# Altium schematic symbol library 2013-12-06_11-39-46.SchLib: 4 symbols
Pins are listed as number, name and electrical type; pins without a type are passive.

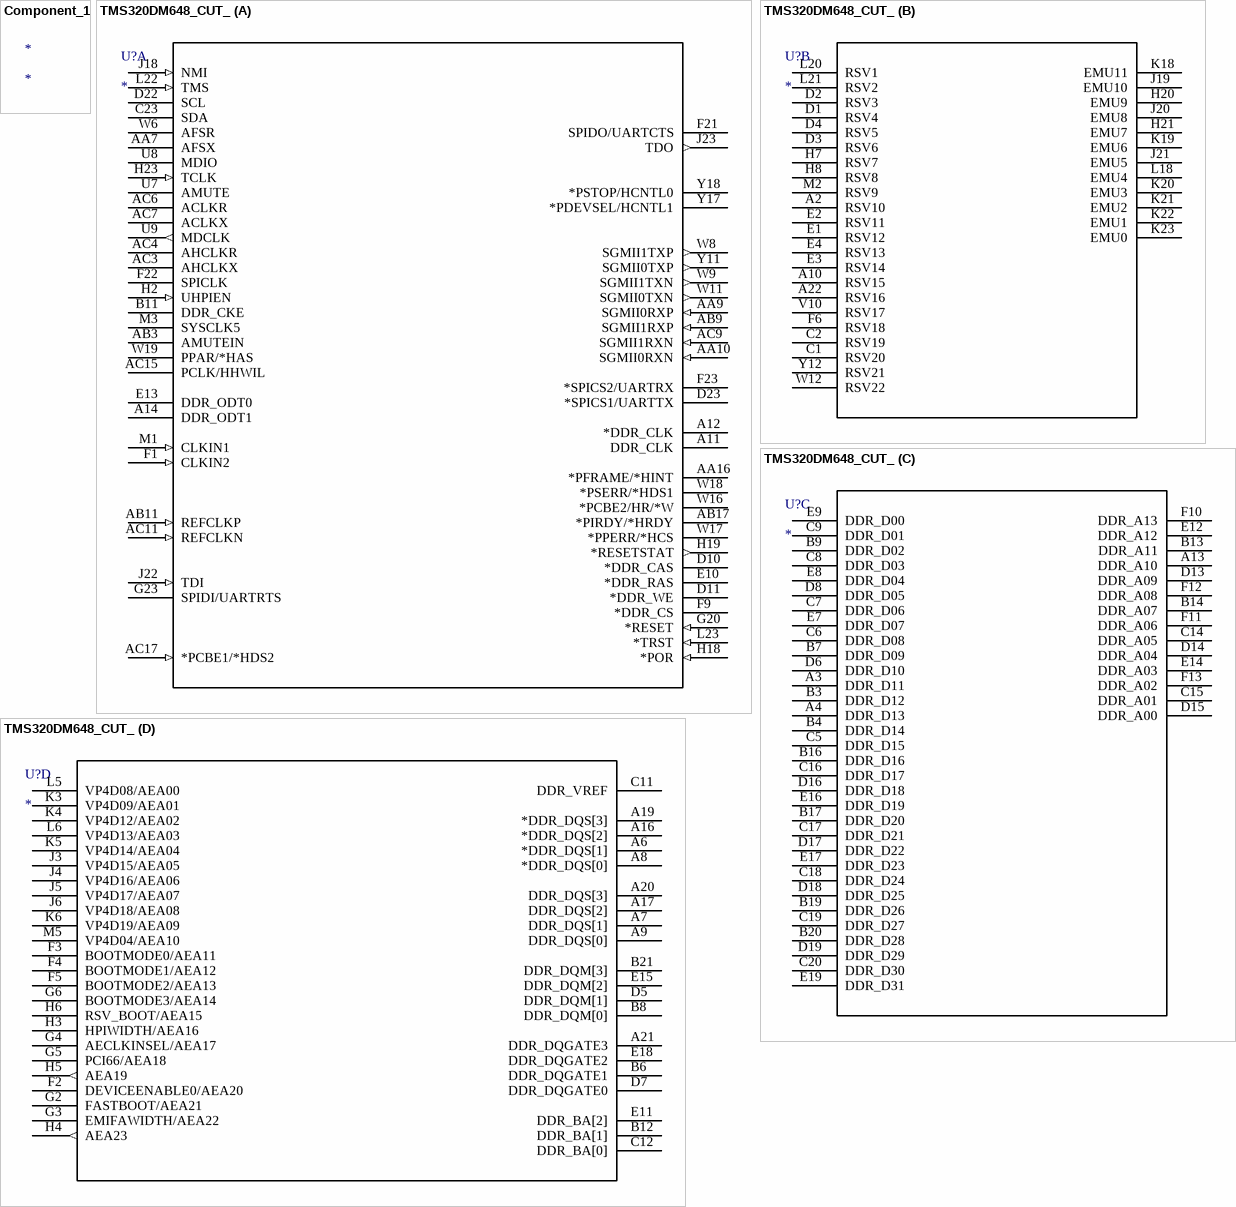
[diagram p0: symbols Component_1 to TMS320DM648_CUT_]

## Component_1
designator *

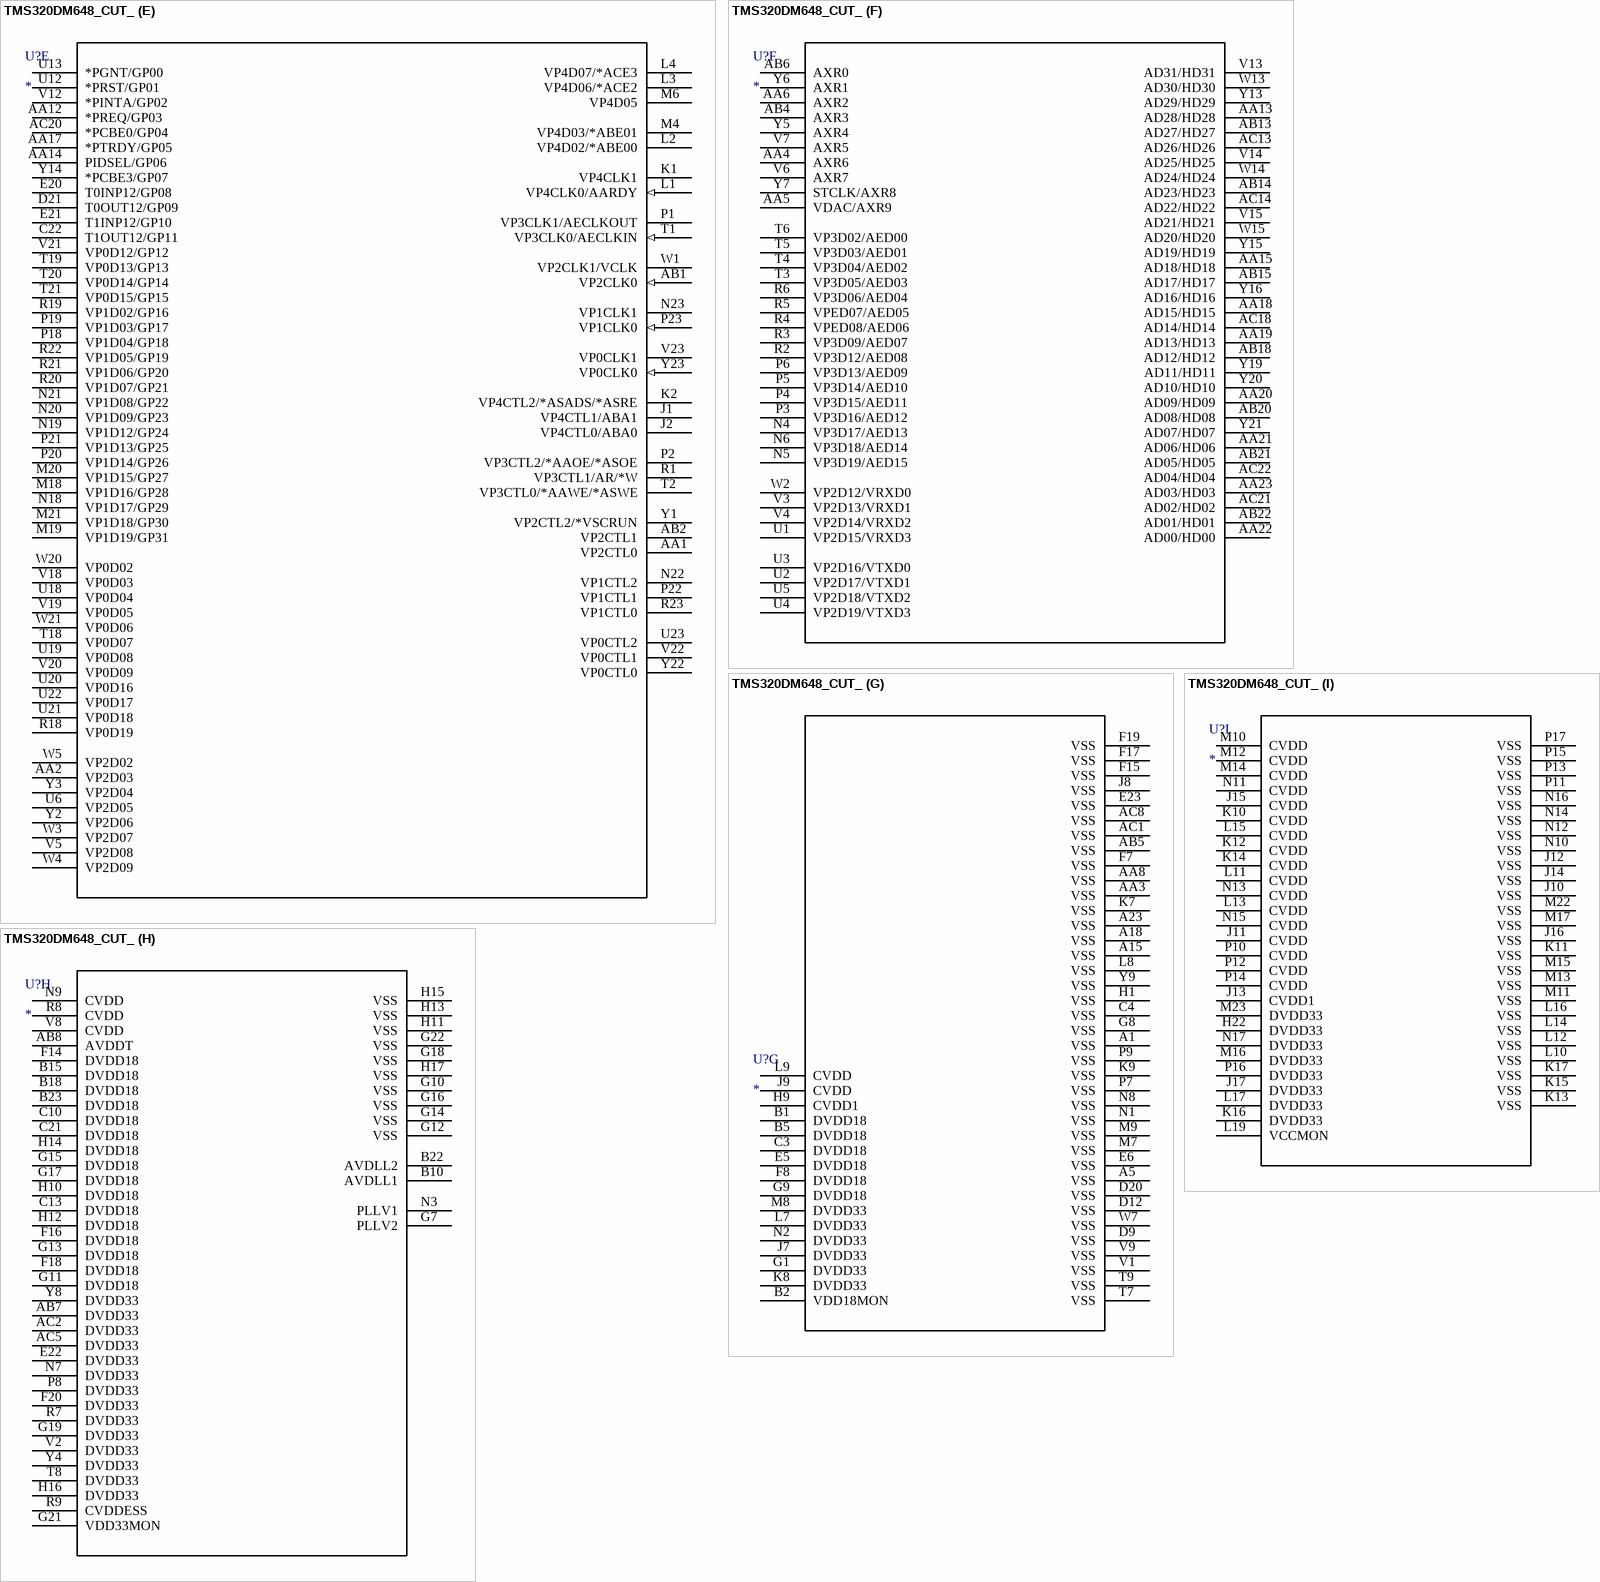
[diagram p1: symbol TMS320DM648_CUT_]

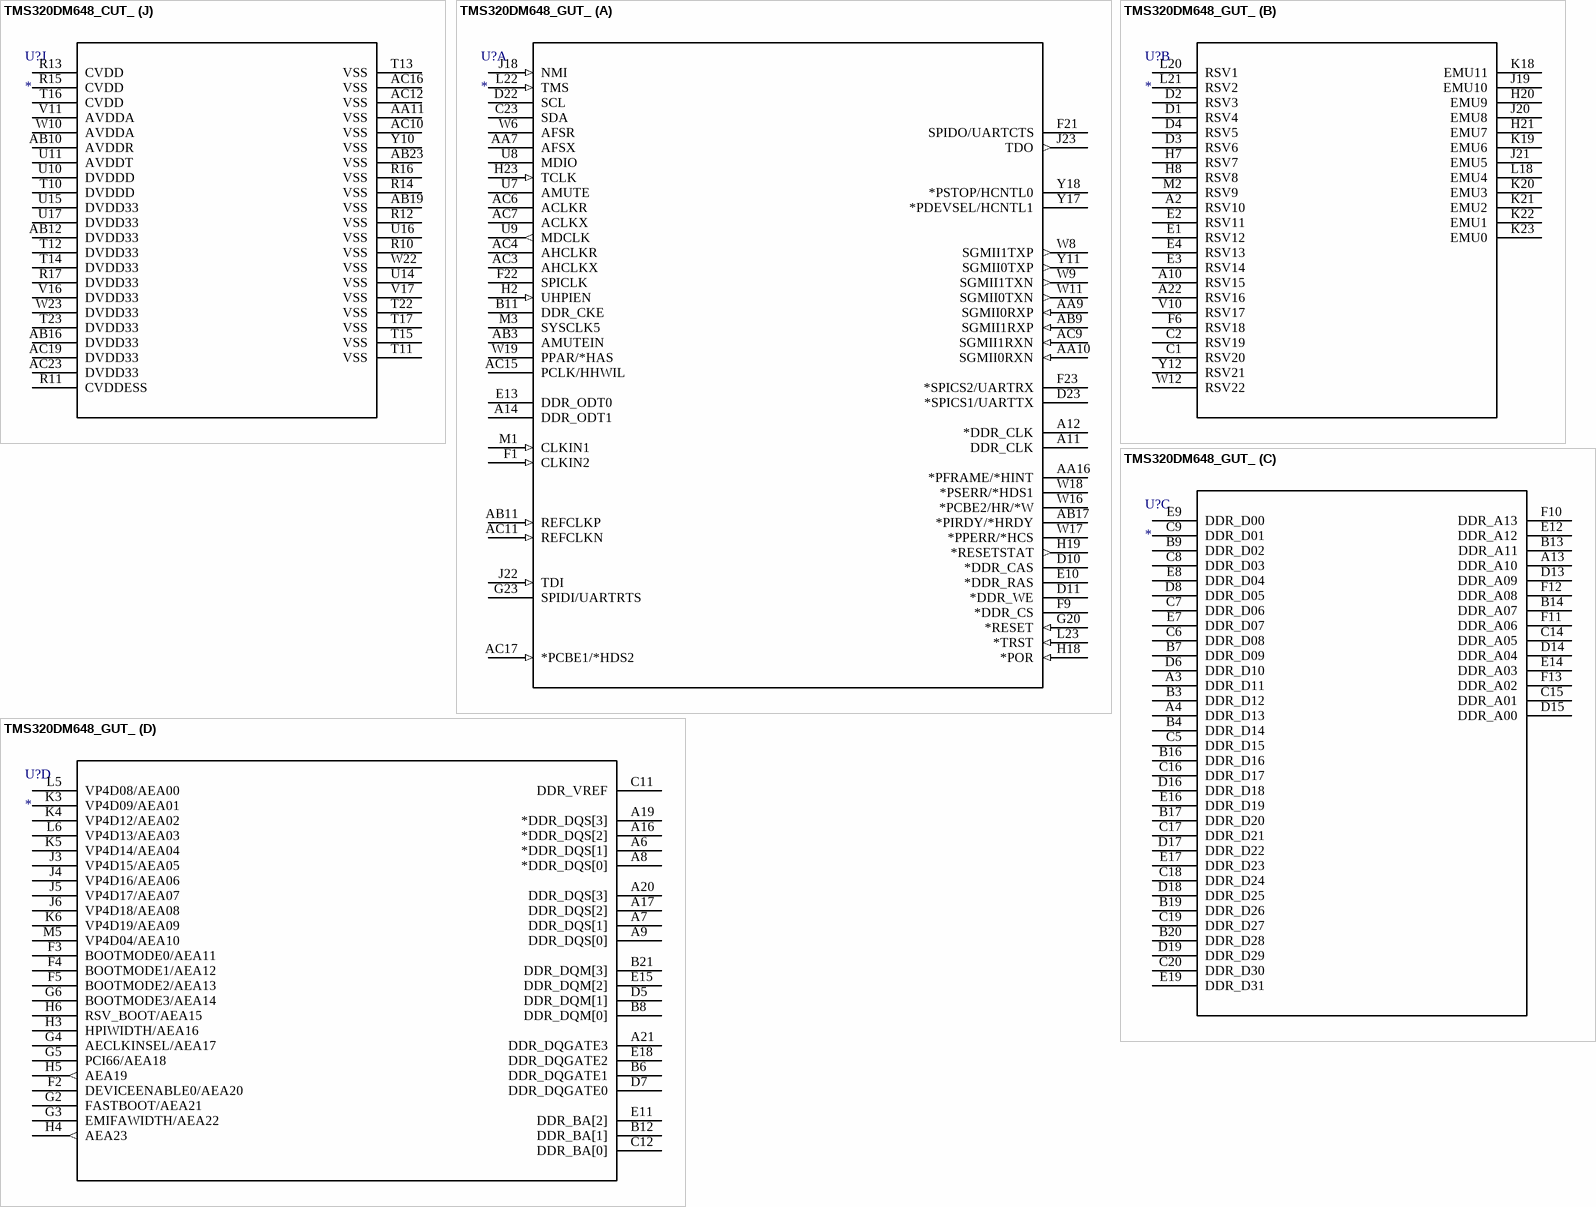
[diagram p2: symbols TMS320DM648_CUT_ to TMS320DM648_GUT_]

## TMS320DM648_CUT_
designator U?
Imported; Manufacturer_Part_Number: tms320dm648_cut_529; Vendor: TEXAS INSTRUMENTS
footprint CUT529
part A pins: A11 DDR_CLK, A12 *DDR_CLK, A14 DDR_ODT1, AA7 AFSX, AA9 SGMII0RXP (in), AA10 SGMII0RXN (in), AA16 *PFRAME/*HINT, AB3 AMUTEIN, AB9 SGMII1RXP (in), AB11 REFCLKP (in), AB17 *PIRDY/*HRDY, AC3 AHCLKX, AC4 AHCLKR, AC6 ACLKR, AC7 ACLKX, AC9 SGMII1RXN (in), AC11 REFCLKN (in), AC15 PCLK/HHWIL, AC17 *PCBE1/*HDS2 (in), B11 DDR_CKE, C23 SDA, D10 *DDR_CAS, D11 *DDR_WE, D22 SCL, D23 *SPICS1/UARTTX, E10 *DDR_RAS, E13 DDR_ODT0, F1 CLKIN2 (in), F9 *DDR_CS, F21 SPIDO/UARTCTS, F22 SPICLK, F23 *SPICS2/UARTRX, G20 *RESET (in), G23 SPIDI/UARTRTS, H2 UHPIEN (in), H18 *POR (in), H19 *RESETSTAT (out), H23 TCLK (in), J18 NMI (in), J22 TDI (in), J23 TDO (out), L22 TMS (in), L23 *TRST (in), M1 CLKIN1 (in), M3 SYSCLK5, U7 AMUTE, U8 MDIO, U9 MDCLK (out), W6 AFSR, W8 SGMII1TXP (out), W9 SGMII1TXN (out), W11 SGMII0TXN (out), W16 *PCBE2/HR/*W, W17 *PPERR/*HCS, W18 *PSERR/*HDS1, W19 PPAR/*HAS, Y11 SGMII0TXP (out), Y17 *PDEVSEL/HCNTL1, Y18 *PSTOP/HCNTL0
part B pins: A2 RSV10, A10 RSV15, A22 RSV16, C1 RSV20, C2 RSV19, D1 RSV4, D2 RSV3, D3 RSV6, D4 RSV5, E1 RSV12, E2 RSV11, E3 RSV14, E4 RSV13, F6 RSV18, H7 RSV7, H8 RSV8, H20 EMU9, H21 EMU7, J19 EMU10, J20 EMU8, J21 EMU5, K18 EMU11, K19 EMU6, K20 EMU3, K21 EMU2, K22 EMU1, K23 EMU0, L18 EMU4, L20 RSV1, L21 RSV2, M2 RSV9, V10 RSV17, W12 RSV22, Y12 RSV21
part C pins: A3 DDR_D11, A4 DDR_D13, A13 DDR_A10, B3 DDR_D12, B4 DDR_D14, B7 DDR_D09, B9 DDR_D02, B13 DDR_A11, B14 DDR_A07, B16 DDR_D16, B17 DDR_D20, B19 DDR_D26, B20 DDR_D28, C5 DDR_D15, C6 DDR_D08, C7 DDR_D06, C8 DDR_D03, C9 DDR_D01, C14 DDR_A05, C15 DDR_A01, C16 DDR_D17, C17 DDR_D21, C18 DDR_D24, C19 DDR_D27, C20 DDR_D30, D6 DDR_D10, D8 DDR_D05, D13 DDR_A09, D14 DDR_A04, D15 DDR_A00, D16 DDR_D18, D17 DDR_D22, D18 DDR_D25, D19 DDR_D29, E7 DDR_D07, E8 DDR_D04, E9 DDR_D00, E12 DDR_A12, E14 DDR_A03, E16 DDR_D19, E17 DDR_D23, E19 DDR_D31, F10 DDR_A13, F11 DDR_A06, F12 DDR_A08, F13 DDR_A02
part D pins: A6 *DDR_DQS[1], A7 DDR_DQS[1], A8 *DDR_DQS[0], A9 DDR_DQS[0], A16 *DDR_DQS[2], A17 DDR_DQS[2], A19 *DDR_DQS[3], A20 DDR_DQS[3], A21 DDR_DQGATE3, B6 DDR_DQGATE1, B8 DDR_DQM[0], B12 DDR_BA[1], B21 DDR_DQM[3], C11 DDR_VREF, C12 DDR_BA[0], D5 DDR_DQM[1], D7 DDR_DQGATE0, E11 DDR_BA[2], E15 DDR_DQM[2], E18 DDR_DQGATE2, F2 DEVICEENABLE0/AEA20, F3 BOOTMODE0/AEA11, F4 BOOTMODE1/AEA12, F5 BOOTMODE2/AEA13, G2 FASTBOOT/AEA21, G3 EMIFAWIDTH/AEA22, G4 AECLKINSEL/AEA17, G5 PCI66/AEA18, G6 BOOTMODE3/AEA14, H3 HPIWIDTH/AEA16, H4 AEA23 (out), H5 AEA19 (out), H6 RSV_BOOT/AEA15, J3 VP4D15/AEA05, J4 VP4D16/AEA06, J5 VP4D17/AEA07, J6 VP4D18/AEA08, K3 VP4D09/AEA01, K4 VP4D12/AEA02, K5 VP4D14/AEA04, K6 VP4D19/AEA09, L5 VP4D08/AEA00, L6 VP4D13/AEA03, M5 VP4D04/AEA10
part E pins: AA1 VP2CTL0, AA2 VP2D03, AA12 *PREQ/GP03, AA14 PIDSEL/GP06, AA17 *PTRDY/GP05, AB1 VP2CLK0 (in), AB2 VP2CTL1, AC20 *PCBE0/GP04, C22 T1OUT12/GP11, D21 T0OUT12/GP09, E20 T0INP12/GP08, E21 T1INP12/GP10, J1 VP4CTL1/ABA1, J2 VP4CTL0/ABA0, K1 VP4CLK1, K2 VP4CTL2/*ASADS/*ASRE, L1 VP4CLK0/AARDY (in), L2 VP4D02/*ABE00, L3 VP4D06/*ACE2, L4 VP4D07/*ACE3, M4 VP4D03/*ABE01, M6 VP4D05, M18 VP1D16/GP28, M19 VP1D19/GP31, M20 VP1D15/GP27, M21 VP1D18/GP30, N18 VP1D17/GP29, N19 VP1D12/GP24, N20 VP1D09/GP23, N21 VP1D08/GP22, N22 VP1CTL2, N23 VP1CLK1, P1 VP3CLK1/AECLKOUT, P2 VP3CTL2/*AAOE/*ASOE, P18 VP1D04/GP18, P19 VP1D03/GP17, P20 VP1D14/GP26, P21 VP1D13/GP25, P22 VP1CTL1, P23 VP1CLK0 (in), R1 VP3CTL1/AR/*W, R18 VP0D19, R19 VP1D02/GP16, R20 VP1D07/GP21, R21 VP1D06/GP20, R22 VP1D05/GP19, R23 VP1CTL0, T1 VP3CLK0/AECLKIN (in), T2 VP3CTL0/*AAWE/*ASWE, T18 VP0D07, T19 VP0D13/GP13, T20 VP0D14/GP14, T21 VP0D15/GP15, U6 VP2D05, U12 *PRST/GP01, U13 *PGNT/GP00, U18 VP0D04, U19 VP0D08, U20 VP0D16, U21 VP0D18, U22 VP0D17, U23 VP0CTL2, V5 VP2D08, V12 *PINTA/GP02, V18 VP0D03, V19 VP0D05, V20 VP0D09, V21 VP0D12/GP12, V22 VP0CTL1, V23 VP0CLK1, W1 VP2CLK1/VCLK, W3 VP2D07, W4 VP2D09, W5 VP2D02, W20 VP0D02, W21 VP0D06, Y1 VP2CTL2/*VSCRUN, Y2 VP2D06, Y3 VP2D04, Y14 *PCBE3/GP07, Y22 VP0CTL0, Y23 VP0CLK0 (in)
part F pins: AA4 AXR6, AA5 VDAC/AXR9, AA6 AXR2, AA13 AD28/HD28, AA15 AD18/HD18, AA18 AD15/HD15, AA19 AD13/HD13, AA20 AD09/HD09, AA21 AD06/HD06, AA22 AD00/HD00, AA23 AD03/HD03, AB4 AXR3, AB6 AXR0, AB13 AD27/HD27, AB14 AD23/HD23, AB15 AD17/HD17, AB18 AD12/HD12, AB20 AD08/HD08, AB21 AD05/HD05, AB22 AD01/HD01, AC13 AD26/HD26, AC14 AD22/HD22, AC18 AD14/HD14, AC21 AD02/HD02, AC22 AD04/HD04, N4 VP3D17/AED13, N5 VP3D19/AED15, N6 VP3D18/AED14, P3 VP3D16/AED12, P4 VP3D15/AED11, P5 VP3D14/AED10, P6 VP3D13/AED09, R2 VP3D12/AED08, R3 VP3D09/AED07, R4 VPED08/AED06, R5 VPED07/AED05, R6 VP3D06/AED04, T3 VP3D05/AED03, T4 VP3D04/AED02, T5 VP3D03/AED01, T6 VP3D02/AED00, U1 VP2D15/VRXD3, U2 VP2D17/VTXD1, U3 VP2D16/VTXD0, U4 VP2D19/VTXD3, U5 VP2D18/VTXD2, V3 VP2D13/VRXD1, V4 VP2D14/VRXD2, V6 AXR7, V7 AXR5, V13 AD31/HD31, V14 AD25/HD25, V15 AD21/HD21, W2 VP2D12/VRXD0, W13 AD30/HD30, W14 AD24/HD24, W15 AD20/HD20, Y5 AXR4, Y6 AXR1, Y7 STCLK/AXR8, Y13 AD29/HD29, Y15 AD19/HD19, Y16 AD16/HD16, Y19 AD11/HD11, Y20 AD10/HD10, Y21 AD07/HD07
part G pins: A1 VSS (power), A5 VSS (power), A15 VSS (power), A18 VSS (power), A23 VSS (power), AA3 VSS (power), AA8 VSS (power), AB5 VSS (power), AC1 VSS (power), AC8 VSS (power), B1 DVDD18 (power), B2 VDD18MON (power), B5 DVDD18 (power), C3 DVDD18 (power), C4 VSS (power), D9 VSS (power), D12 VSS (power), D20 VSS (power), E5 DVDD18 (power), E6 VSS (power), E23 VSS (power), F7 VSS (power), F8 DVDD18 (power), F15 VSS (power), F17 VSS (power), F19 VSS (power), G1 DVDD33 (power), G8 VSS (power), G9 DVDD18 (power), H1 VSS (power), H9 CVDD1 (power), J7 DVDD33 (power), J8 VSS (power), J9 CVDD (power), K7 VSS (power), K8 DVDD33 (power), K9 VSS (power), L7 DVDD33 (power), L8 VSS (power), L9 CVDD (power), M7 VSS (power), M8 DVDD33 (power), M9 VSS (power), N1 VSS (power), N2 DVDD33 (power), N8 VSS (power), P7 VSS (power), P9 VSS (power), T7 VSS (power), T9 VSS (power), V1 VSS (power), V9 VSS (power), W7 VSS (power), Y9 VSS (power)
part H pins: AB7 DVDD33 (power), AB8 AVDDT (power), AC2 DVDD33 (power), AC5 DVDD33 (power), B10 AVDLL1 (power), B15 DVDD18 (power), B18 DVDD18 (power), B22 AVDLL2 (power), B23 DVDD18 (power), C10 DVDD18 (power), C13 DVDD18 (power), C21 DVDD18 (power), E22 DVDD33 (power), F14 DVDD18 (power), F16 DVDD18 (power), F18 DVDD18 (power), F20 DVDD33 (power), G7 PLLV2, G10 VSS (power), G11 DVDD18 (power), G12 VSS (power), G13 DVDD18 (power), G14 VSS (power), G15 DVDD18 (power), G16 VSS (power), G17 DVDD18 (power), G18 VSS (power), G19 DVDD33 (power), G21 VDD33MON (power), G22 VSS (power), H10 DVDD18 (power), H11 VSS (power), H12 DVDD18 (power), H13 VSS (power), H14 DVDD18 (power), H15 VSS (power), H16 DVDD33 (power), H17 VSS (power), N3 PLLV1, N7 DVDD33 (power), N9 CVDD (power), P8 DVDD33 (power), R7 DVDD33 (power), R8 CVDD (power), R9 CVDDESS (power), T8 DVDD33 (power), V2 DVDD33 (power), V8 CVDD (power), Y4 DVDD33 (power), Y8 DVDD33 (power)
part I pins: H22 DVDD33 (power), J10 VSS (power), J11 CVDD (power), J12 VSS (power), J13 CVDD1 (power), J14 VSS (power), J15 CVDD (power), J16 VSS (power), J17 DVDD33 (power), K10 CVDD (power), K11 VSS (power), K12 CVDD (power), K13 VSS (power), K14 CVDD (power), K15 VSS (power), K16 DVDD33 (power), K17 VSS (power), L10 VSS (power), L11 CVDD (power), L12 VSS (power), L13 CVDD (power), L14 VSS (power), L15 CVDD (power), L16 VSS (power), L17 DVDD33 (power), L19 VCCMON (power), M10 CVDD (power), M11 VSS (power), M12 CVDD (power), M13 VSS (power), M14 CVDD (power), M15 VSS (power), M16 DVDD33 (power), M17 VSS (power), M22 VSS (power), M23 DVDD33 (power), N10 VSS (power), N11 CVDD (power), N12 VSS (power), N13 CVDD (power), N14 VSS (power), N15 CVDD (power), N16 VSS (power), N17 DVDD33 (power), P10 CVDD (power), P11 VSS (power), P12 CVDD (power), P13 VSS (power), P14 CVDD (power), P15 VSS (power), P16 DVDD33 (power), P17 VSS (power)
part J pins: AA11 VSS (power), AB10 AVDDR (power), AB12 DVDD33 (power), AB16 DVDD33 (power), AB19 VSS (power), AB23 VSS (power), AC10 VSS (power), AC12 VSS (power), AC16 VSS (power), AC19 DVDD33 (power), AC23 DVDD33 (power), R10 VSS (power), R11 CVDDESS (power), R12 VSS (power), R13 CVDD (power), R14 VSS (power), R15 CVDD (power), R16 VSS (power), R17 DVDD33 (power), T10 DVDDD (power), T11 VSS (power), T12 DVDD33 (power), T13 VSS (power), T14 DVDD33 (power), T15 VSS (power), T16 CVDD (power), T17 VSS (power), T22 VSS (power), T23 DVDD33 (power), U10 DVDDD (power), U11 AVDDT (power), U14 VSS (power), U15 DVDD33 (power), U16 VSS (power), U17 DVDD33 (power), V11 AVDDA (power), V16 DVDD33 (power), V17 VSS (power), W10 AVDDA (power), W22 VSS (power), W23 DVDD33 (power), Y10 VSS (power)

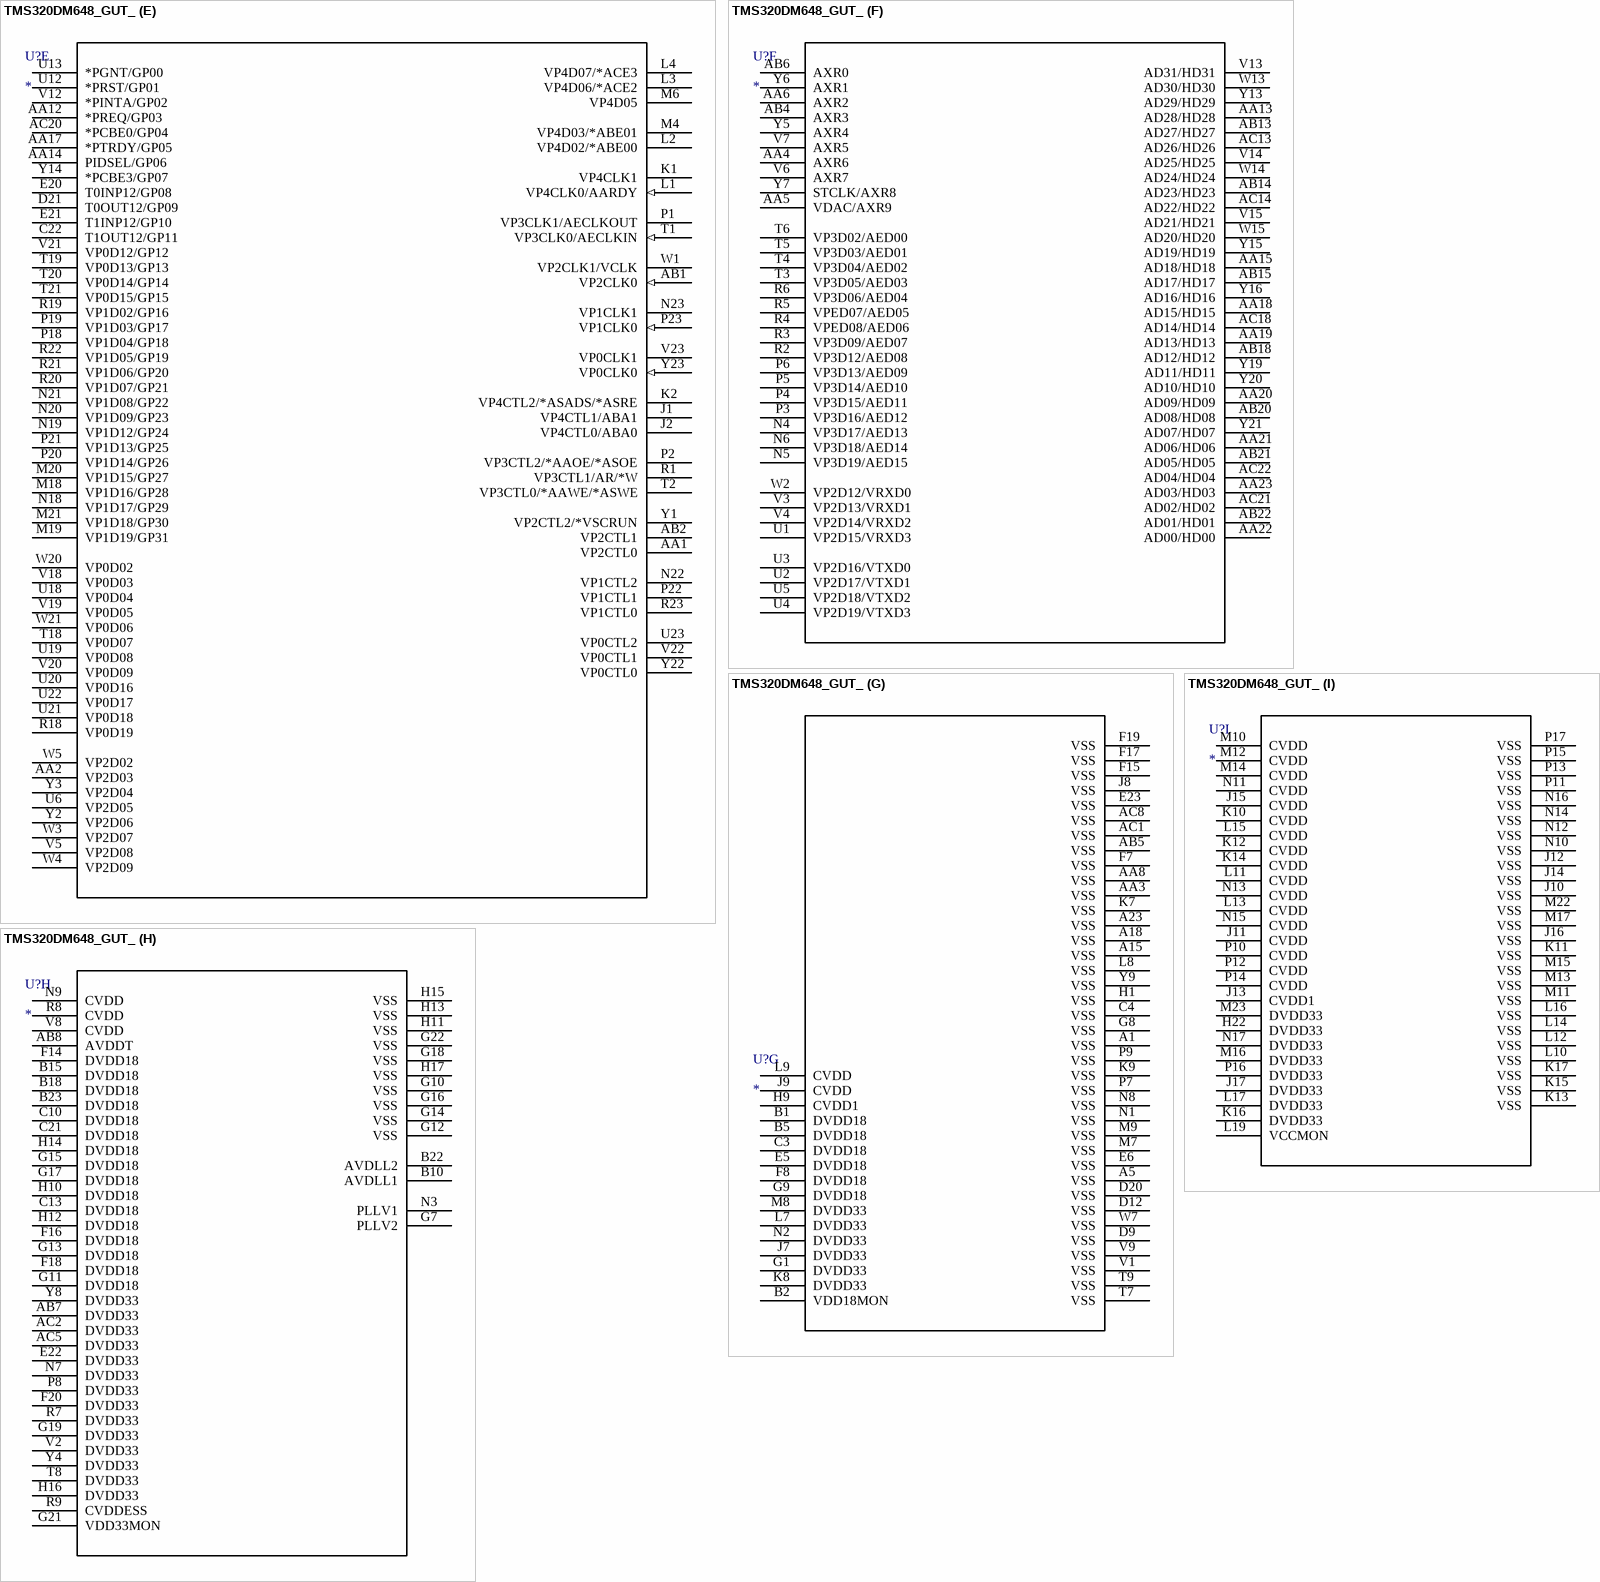
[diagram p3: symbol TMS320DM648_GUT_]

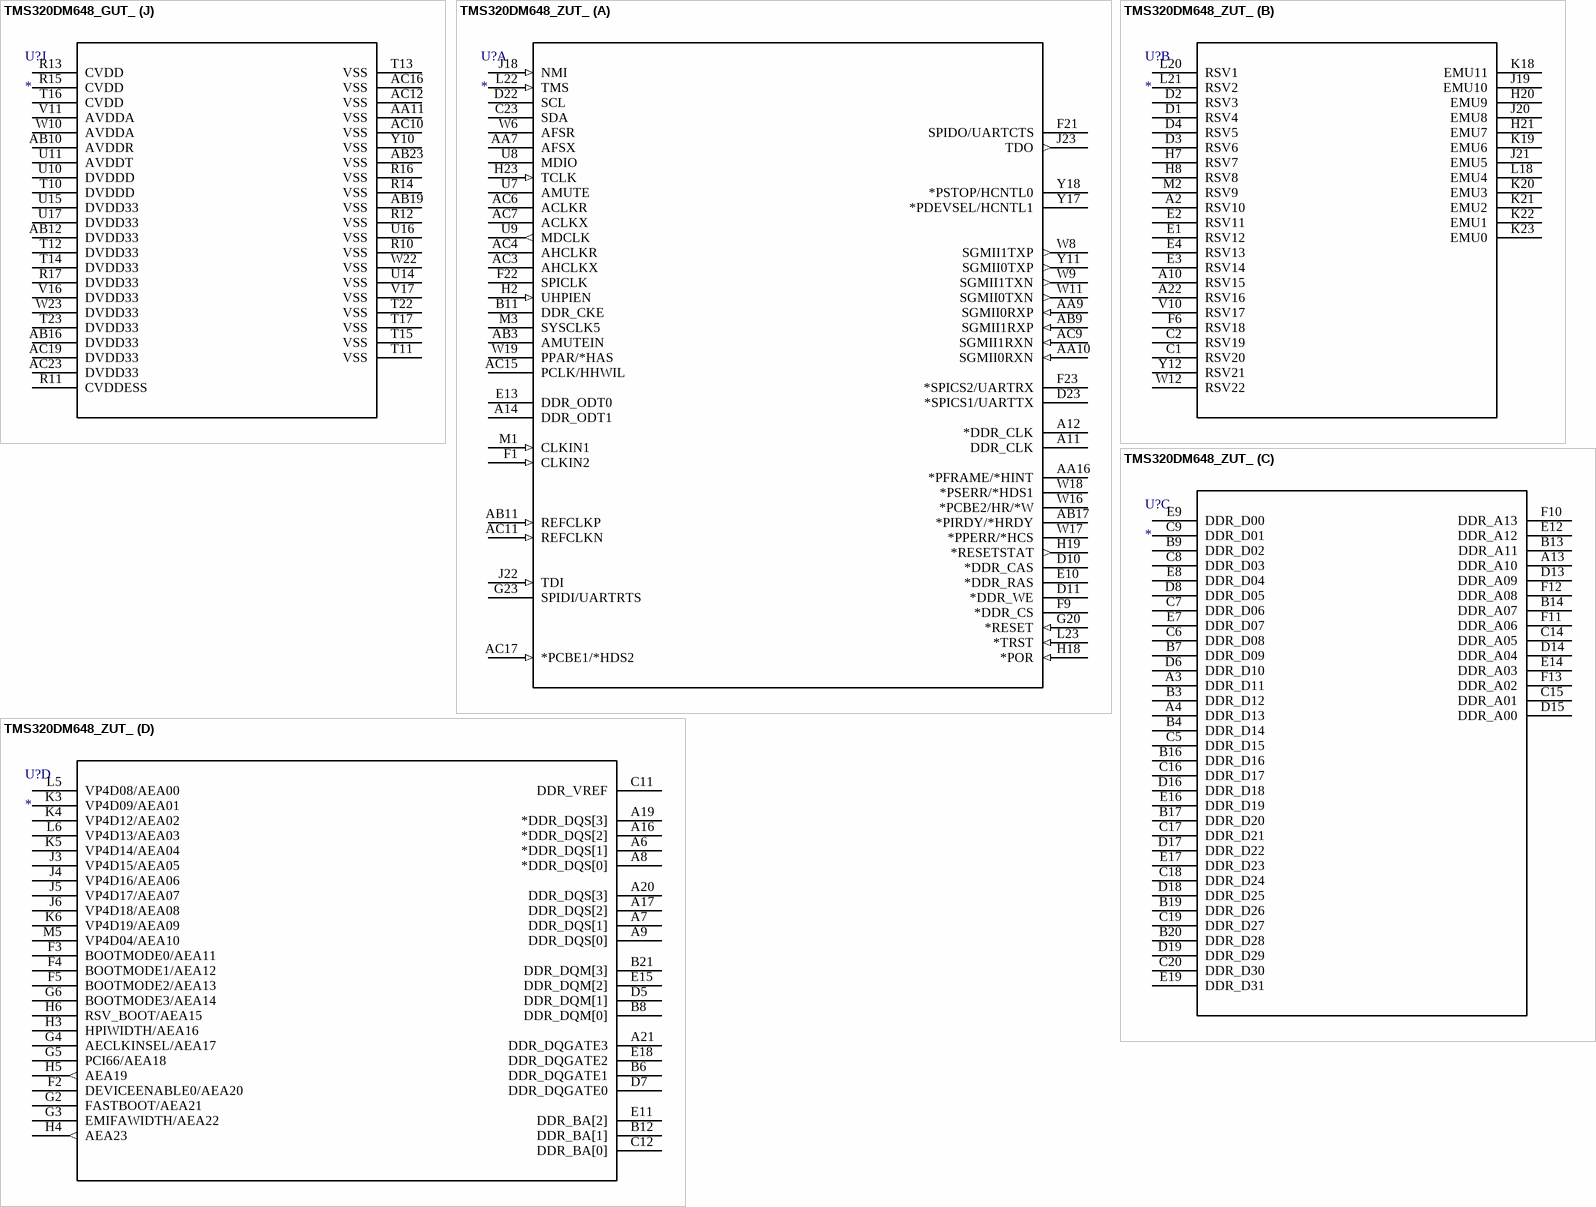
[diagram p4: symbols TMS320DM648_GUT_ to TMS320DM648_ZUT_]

## TMS320DM648_GUT_
designator U?
Imported; Manufacturer_Part_Number: tms320dm648_cut_529; Vendor: TEXAS INSTRUMENTS
footprint GUT529
part A pins: A11 DDR_CLK, A12 *DDR_CLK, A14 DDR_ODT1, AA7 AFSX, AA9 SGMII0RXP (in), AA10 SGMII0RXN (in), AA16 *PFRAME/*HINT, AB3 AMUTEIN, AB9 SGMII1RXP (in), AB11 REFCLKP (in), AB17 *PIRDY/*HRDY, AC3 AHCLKX, AC4 AHCLKR, AC6 ACLKR, AC7 ACLKX, AC9 SGMII1RXN (in), AC11 REFCLKN (in), AC15 PCLK/HHWIL, AC17 *PCBE1/*HDS2 (in), B11 DDR_CKE, C23 SDA, D10 *DDR_CAS, D11 *DDR_WE, D22 SCL, D23 *SPICS1/UARTTX, E10 *DDR_RAS, E13 DDR_ODT0, F1 CLKIN2 (in), F9 *DDR_CS, F21 SPIDO/UARTCTS, F22 SPICLK, F23 *SPICS2/UARTRX, G20 *RESET (in), G23 SPIDI/UARTRTS, H2 UHPIEN (in), H18 *POR (in), H19 *RESETSTAT (out), H23 TCLK (in), J18 NMI (in), J22 TDI (in), J23 TDO (out), L22 TMS (in), L23 *TRST (in), M1 CLKIN1 (in), M3 SYSCLK5, U7 AMUTE, U8 MDIO, U9 MDCLK (out), W6 AFSR, W8 SGMII1TXP (out), W9 SGMII1TXN (out), W11 SGMII0TXN (out), W16 *PCBE2/HR/*W, W17 *PPERR/*HCS, W18 *PSERR/*HDS1, W19 PPAR/*HAS, Y11 SGMII0TXP (out), Y17 *PDEVSEL/HCNTL1, Y18 *PSTOP/HCNTL0
part B pins: A2 RSV10, A10 RSV15, A22 RSV16, C1 RSV20, C2 RSV19, D1 RSV4, D2 RSV3, D3 RSV6, D4 RSV5, E1 RSV12, E2 RSV11, E3 RSV14, E4 RSV13, F6 RSV18, H7 RSV7, H8 RSV8, H20 EMU9, H21 EMU7, J19 EMU10, J20 EMU8, J21 EMU5, K18 EMU11, K19 EMU6, K20 EMU3, K21 EMU2, K22 EMU1, K23 EMU0, L18 EMU4, L20 RSV1, L21 RSV2, M2 RSV9, V10 RSV17, W12 RSV22, Y12 RSV21
part C pins: A3 DDR_D11, A4 DDR_D13, A13 DDR_A10, B3 DDR_D12, B4 DDR_D14, B7 DDR_D09, B9 DDR_D02, B13 DDR_A11, B14 DDR_A07, B16 DDR_D16, B17 DDR_D20, B19 DDR_D26, B20 DDR_D28, C5 DDR_D15, C6 DDR_D08, C7 DDR_D06, C8 DDR_D03, C9 DDR_D01, C14 DDR_A05, C15 DDR_A01, C16 DDR_D17, C17 DDR_D21, C18 DDR_D24, C19 DDR_D27, C20 DDR_D30, D6 DDR_D10, D8 DDR_D05, D13 DDR_A09, D14 DDR_A04, D15 DDR_A00, D16 DDR_D18, D17 DDR_D22, D18 DDR_D25, D19 DDR_D29, E7 DDR_D07, E8 DDR_D04, E9 DDR_D00, E12 DDR_A12, E14 DDR_A03, E16 DDR_D19, E17 DDR_D23, E19 DDR_D31, F10 DDR_A13, F11 DDR_A06, F12 DDR_A08, F13 DDR_A02
part D pins: A6 *DDR_DQS[1], A7 DDR_DQS[1], A8 *DDR_DQS[0], A9 DDR_DQS[0], A16 *DDR_DQS[2], A17 DDR_DQS[2], A19 *DDR_DQS[3], A20 DDR_DQS[3], A21 DDR_DQGATE3, B6 DDR_DQGATE1, B8 DDR_DQM[0], B12 DDR_BA[1], B21 DDR_DQM[3], C11 DDR_VREF, C12 DDR_BA[0], D5 DDR_DQM[1], D7 DDR_DQGATE0, E11 DDR_BA[2], E15 DDR_DQM[2], E18 DDR_DQGATE2, F2 DEVICEENABLE0/AEA20, F3 BOOTMODE0/AEA11, F4 BOOTMODE1/AEA12, F5 BOOTMODE2/AEA13, G2 FASTBOOT/AEA21, G3 EMIFAWIDTH/AEA22, G4 AECLKINSEL/AEA17, G5 PCI66/AEA18, G6 BOOTMODE3/AEA14, H3 HPIWIDTH/AEA16, H4 AEA23 (out), H5 AEA19 (out), H6 RSV_BOOT/AEA15, J3 VP4D15/AEA05, J4 VP4D16/AEA06, J5 VP4D17/AEA07, J6 VP4D18/AEA08, K3 VP4D09/AEA01, K4 VP4D12/AEA02, K5 VP4D14/AEA04, K6 VP4D19/AEA09, L5 VP4D08/AEA00, L6 VP4D13/AEA03, M5 VP4D04/AEA10
part E pins: AA1 VP2CTL0, AA2 VP2D03, AA12 *PREQ/GP03, AA14 PIDSEL/GP06, AA17 *PTRDY/GP05, AB1 VP2CLK0 (in), AB2 VP2CTL1, AC20 *PCBE0/GP04, C22 T1OUT12/GP11, D21 T0OUT12/GP09, E20 T0INP12/GP08, E21 T1INP12/GP10, J1 VP4CTL1/ABA1, J2 VP4CTL0/ABA0, K1 VP4CLK1, K2 VP4CTL2/*ASADS/*ASRE, L1 VP4CLK0/AARDY (in), L2 VP4D02/*ABE00, L3 VP4D06/*ACE2, L4 VP4D07/*ACE3, M4 VP4D03/*ABE01, M6 VP4D05, M18 VP1D16/GP28, M19 VP1D19/GP31, M20 VP1D15/GP27, M21 VP1D18/GP30, N18 VP1D17/GP29, N19 VP1D12/GP24, N20 VP1D09/GP23, N21 VP1D08/GP22, N22 VP1CTL2, N23 VP1CLK1, P1 VP3CLK1/AECLKOUT, P2 VP3CTL2/*AAOE/*ASOE, P18 VP1D04/GP18, P19 VP1D03/GP17, P20 VP1D14/GP26, P21 VP1D13/GP25, P22 VP1CTL1, P23 VP1CLK0 (in), R1 VP3CTL1/AR/*W, R18 VP0D19, R19 VP1D02/GP16, R20 VP1D07/GP21, R21 VP1D06/GP20, R22 VP1D05/GP19, R23 VP1CTL0, T1 VP3CLK0/AECLKIN (in), T2 VP3CTL0/*AAWE/*ASWE, T18 VP0D07, T19 VP0D13/GP13, T20 VP0D14/GP14, T21 VP0D15/GP15, U6 VP2D05, U12 *PRST/GP01, U13 *PGNT/GP00, U18 VP0D04, U19 VP0D08, U20 VP0D16, U21 VP0D18, U22 VP0D17, U23 VP0CTL2, V5 VP2D08, V12 *PINTA/GP02, V18 VP0D03, V19 VP0D05, V20 VP0D09, V21 VP0D12/GP12, V22 VP0CTL1, V23 VP0CLK1, W1 VP2CLK1/VCLK, W3 VP2D07, W4 VP2D09, W5 VP2D02, W20 VP0D02, W21 VP0D06, Y1 VP2CTL2/*VSCRUN, Y2 VP2D06, Y3 VP2D04, Y14 *PCBE3/GP07, Y22 VP0CTL0, Y23 VP0CLK0 (in)
part F pins: AA4 AXR6, AA5 VDAC/AXR9, AA6 AXR2, AA13 AD28/HD28, AA15 AD18/HD18, AA18 AD15/HD15, AA19 AD13/HD13, AA20 AD09/HD09, AA21 AD06/HD06, AA22 AD00/HD00, AA23 AD03/HD03, AB4 AXR3, AB6 AXR0, AB13 AD27/HD27, AB14 AD23/HD23, AB15 AD17/HD17, AB18 AD12/HD12, AB20 AD08/HD08, AB21 AD05/HD05, AB22 AD01/HD01, AC13 AD26/HD26, AC14 AD22/HD22, AC18 AD14/HD14, AC21 AD02/HD02, AC22 AD04/HD04, N4 VP3D17/AED13, N5 VP3D19/AED15, N6 VP3D18/AED14, P3 VP3D16/AED12, P4 VP3D15/AED11, P5 VP3D14/AED10, P6 VP3D13/AED09, R2 VP3D12/AED08, R3 VP3D09/AED07, R4 VPED08/AED06, R5 VPED07/AED05, R6 VP3D06/AED04, T3 VP3D05/AED03, T4 VP3D04/AED02, T5 VP3D03/AED01, T6 VP3D02/AED00, U1 VP2D15/VRXD3, U2 VP2D17/VTXD1, U3 VP2D16/VTXD0, U4 VP2D19/VTXD3, U5 VP2D18/VTXD2, V3 VP2D13/VRXD1, V4 VP2D14/VRXD2, V6 AXR7, V7 AXR5, V13 AD31/HD31, V14 AD25/HD25, V15 AD21/HD21, W2 VP2D12/VRXD0, W13 AD30/HD30, W14 AD24/HD24, W15 AD20/HD20, Y5 AXR4, Y6 AXR1, Y7 STCLK/AXR8, Y13 AD29/HD29, Y15 AD19/HD19, Y16 AD16/HD16, Y19 AD11/HD11, Y20 AD10/HD10, Y21 AD07/HD07
part G pins: A1 VSS (power), A5 VSS (power), A15 VSS (power), A18 VSS (power), A23 VSS (power), AA3 VSS (power), AA8 VSS (power), AB5 VSS (power), AC1 VSS (power), AC8 VSS (power), B1 DVDD18 (power), B2 VDD18MON (power), B5 DVDD18 (power), C3 DVDD18 (power), C4 VSS (power), D9 VSS (power), D12 VSS (power), D20 VSS (power), E5 DVDD18 (power), E6 VSS (power), E23 VSS (power), F7 VSS (power), F8 DVDD18 (power), F15 VSS (power), F17 VSS (power), F19 VSS (power), G1 DVDD33 (power), G8 VSS (power), G9 DVDD18 (power), H1 VSS (power), H9 CVDD1 (power), J7 DVDD33 (power), J8 VSS (power), J9 CVDD (power), K7 VSS (power), K8 DVDD33 (power), K9 VSS (power), L7 DVDD33 (power), L8 VSS (power), L9 CVDD (power), M7 VSS (power), M8 DVDD33 (power), M9 VSS (power), N1 VSS (power), N2 DVDD33 (power), N8 VSS (power), P7 VSS (power), P9 VSS (power), T7 VSS (power), T9 VSS (power), V1 VSS (power), V9 VSS (power), W7 VSS (power), Y9 VSS (power)
part H pins: AB7 DVDD33 (power), AB8 AVDDT (power), AC2 DVDD33 (power), AC5 DVDD33 (power), B10 AVDLL1 (power), B15 DVDD18 (power), B18 DVDD18 (power), B22 AVDLL2 (power), B23 DVDD18 (power), C10 DVDD18 (power), C13 DVDD18 (power), C21 DVDD18 (power), E22 DVDD33 (power), F14 DVDD18 (power), F16 DVDD18 (power), F18 DVDD18 (power), F20 DVDD33 (power), G7 PLLV2, G10 VSS (power), G11 DVDD18 (power), G12 VSS (power), G13 DVDD18 (power), G14 VSS (power), G15 DVDD18 (power), G16 VSS (power), G17 DVDD18 (power), G18 VSS (power), G19 DVDD33 (power), G21 VDD33MON (power), G22 VSS (power), H10 DVDD18 (power), H11 VSS (power), H12 DVDD18 (power), H13 VSS (power), H14 DVDD18 (power), H15 VSS (power), H16 DVDD33 (power), H17 VSS (power), N3 PLLV1, N7 DVDD33 (power), N9 CVDD (power), P8 DVDD33 (power), R7 DVDD33 (power), R8 CVDD (power), R9 CVDDESS (power), T8 DVDD33 (power), V2 DVDD33 (power), V8 CVDD (power), Y4 DVDD33 (power), Y8 DVDD33 (power)
part I pins: H22 DVDD33 (power), J10 VSS (power), J11 CVDD (power), J12 VSS (power), J13 CVDD1 (power), J14 VSS (power), J15 CVDD (power), J16 VSS (power), J17 DVDD33 (power), K10 CVDD (power), K11 VSS (power), K12 CVDD (power), K13 VSS (power), K14 CVDD (power), K15 VSS (power), K16 DVDD33 (power), K17 VSS (power), L10 VSS (power), L11 CVDD (power), L12 VSS (power), L13 CVDD (power), L14 VSS (power), L15 CVDD (power), L16 VSS (power), L17 DVDD33 (power), L19 VCCMON (power), M10 CVDD (power), M11 VSS (power), M12 CVDD (power), M13 VSS (power), M14 CVDD (power), M15 VSS (power), M16 DVDD33 (power), M17 VSS (power), M22 VSS (power), M23 DVDD33 (power), N10 VSS (power), N11 CVDD (power), N12 VSS (power), N13 CVDD (power), N14 VSS (power), N15 CVDD (power), N16 VSS (power), N17 DVDD33 (power), P10 CVDD (power), P11 VSS (power), P12 CVDD (power), P13 VSS (power), P14 CVDD (power), P15 VSS (power), P16 DVDD33 (power), P17 VSS (power)
part J pins: AA11 VSS (power), AB10 AVDDR (power), AB12 DVDD33 (power), AB16 DVDD33 (power), AB19 VSS (power), AB23 VSS (power), AC10 VSS (power), AC12 VSS (power), AC16 VSS (power), AC19 DVDD33 (power), AC23 DVDD33 (power), R10 VSS (power), R11 CVDDESS (power), R12 VSS (power), R13 CVDD (power), R14 VSS (power), R15 CVDD (power), R16 VSS (power), R17 DVDD33 (power), T10 DVDDD (power), T11 VSS (power), T12 DVDD33 (power), T13 VSS (power), T14 DVDD33 (power), T15 VSS (power), T16 CVDD (power), T17 VSS (power), T22 VSS (power), T23 DVDD33 (power), U10 DVDDD (power), U11 AVDDT (power), U14 VSS (power), U15 DVDD33 (power), U16 VSS (power), U17 DVDD33 (power), V11 AVDDA (power), V16 DVDD33 (power), V17 VSS (power), W10 AVDDA (power), W22 VSS (power), W23 DVDD33 (power), Y10 VSS (power)

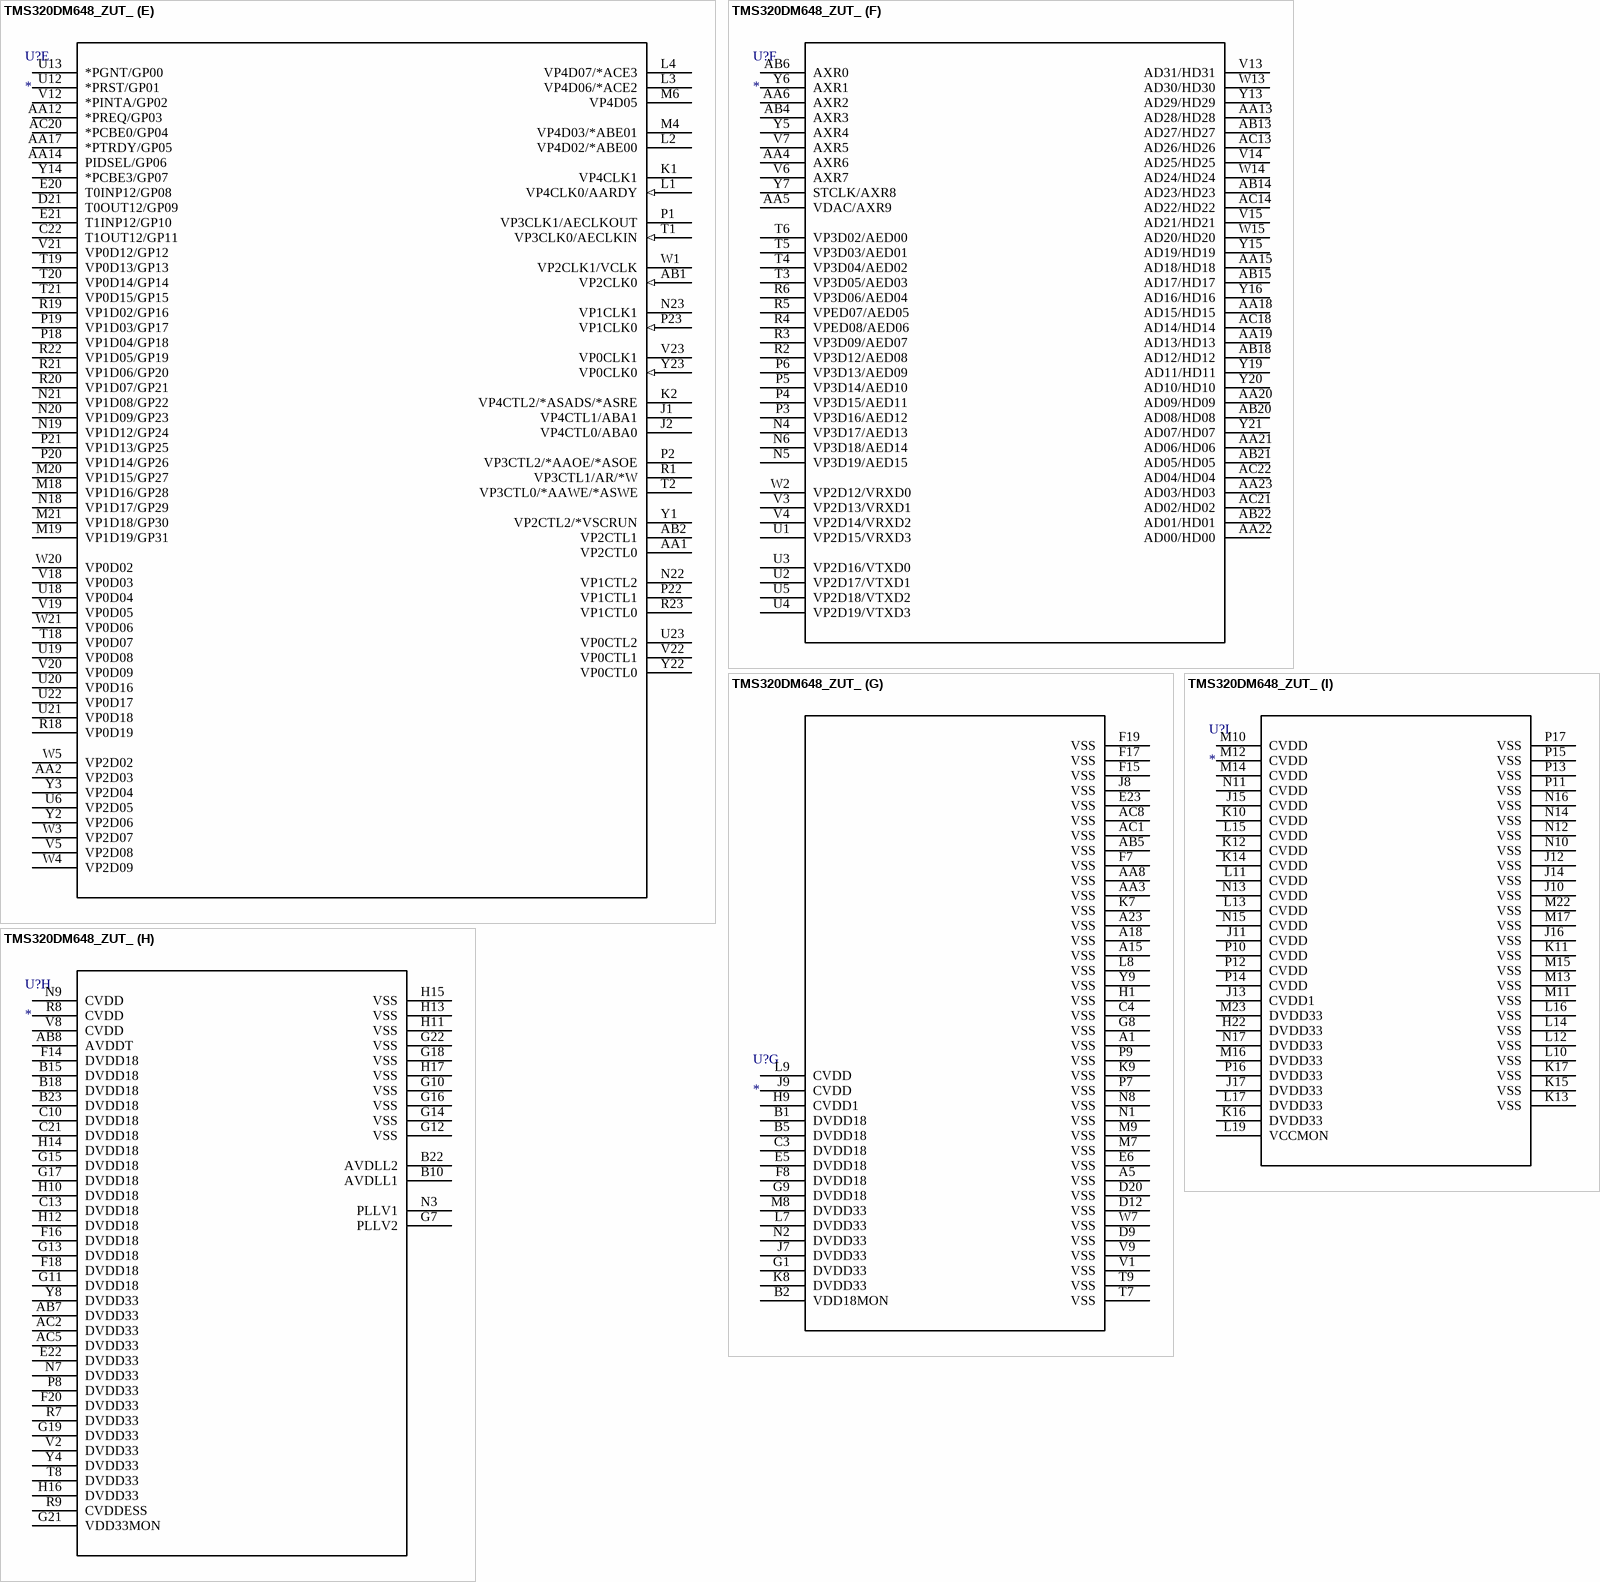
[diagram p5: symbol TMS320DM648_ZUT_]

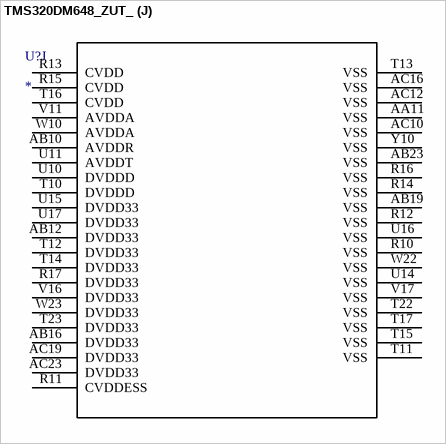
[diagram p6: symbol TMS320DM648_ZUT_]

## TMS320DM648_ZUT_
designator U?
Imported; Manufacturer_Part_Number: tms320dm648_cut_529; Vendor: TEXAS INSTRUMENTS
footprint ZUT529
part A pins: A11 DDR_CLK, A12 *DDR_CLK, A14 DDR_ODT1, AA7 AFSX, AA9 SGMII0RXP (in), AA10 SGMII0RXN (in), AA16 *PFRAME/*HINT, AB3 AMUTEIN, AB9 SGMII1RXP (in), AB11 REFCLKP (in), AB17 *PIRDY/*HRDY, AC3 AHCLKX, AC4 AHCLKR, AC6 ACLKR, AC7 ACLKX, AC9 SGMII1RXN (in), AC11 REFCLKN (in), AC15 PCLK/HHWIL, AC17 *PCBE1/*HDS2 (in), B11 DDR_CKE, C23 SDA, D10 *DDR_CAS, D11 *DDR_WE, D22 SCL, D23 *SPICS1/UARTTX, E10 *DDR_RAS, E13 DDR_ODT0, F1 CLKIN2 (in), F9 *DDR_CS, F21 SPIDO/UARTCTS, F22 SPICLK, F23 *SPICS2/UARTRX, G20 *RESET (in), G23 SPIDI/UARTRTS, H2 UHPIEN (in), H18 *POR (in), H19 *RESETSTAT (out), H23 TCLK (in), J18 NMI (in), J22 TDI (in), J23 TDO (out), L22 TMS (in), L23 *TRST (in), M1 CLKIN1 (in), M3 SYSCLK5, U7 AMUTE, U8 MDIO, U9 MDCLK (out), W6 AFSR, W8 SGMII1TXP (out), W9 SGMII1TXN (out), W11 SGMII0TXN (out), W16 *PCBE2/HR/*W, W17 *PPERR/*HCS, W18 *PSERR/*HDS1, W19 PPAR/*HAS, Y11 SGMII0TXP (out), Y17 *PDEVSEL/HCNTL1, Y18 *PSTOP/HCNTL0
part B pins: A2 RSV10, A10 RSV15, A22 RSV16, C1 RSV20, C2 RSV19, D1 RSV4, D2 RSV3, D3 RSV6, D4 RSV5, E1 RSV12, E2 RSV11, E3 RSV14, E4 RSV13, F6 RSV18, H7 RSV7, H8 RSV8, H20 EMU9, H21 EMU7, J19 EMU10, J20 EMU8, J21 EMU5, K18 EMU11, K19 EMU6, K20 EMU3, K21 EMU2, K22 EMU1, K23 EMU0, L18 EMU4, L20 RSV1, L21 RSV2, M2 RSV9, V10 RSV17, W12 RSV22, Y12 RSV21
part C pins: A3 DDR_D11, A4 DDR_D13, A13 DDR_A10, B3 DDR_D12, B4 DDR_D14, B7 DDR_D09, B9 DDR_D02, B13 DDR_A11, B14 DDR_A07, B16 DDR_D16, B17 DDR_D20, B19 DDR_D26, B20 DDR_D28, C5 DDR_D15, C6 DDR_D08, C7 DDR_D06, C8 DDR_D03, C9 DDR_D01, C14 DDR_A05, C15 DDR_A01, C16 DDR_D17, C17 DDR_D21, C18 DDR_D24, C19 DDR_D27, C20 DDR_D30, D6 DDR_D10, D8 DDR_D05, D13 DDR_A09, D14 DDR_A04, D15 DDR_A00, D16 DDR_D18, D17 DDR_D22, D18 DDR_D25, D19 DDR_D29, E7 DDR_D07, E8 DDR_D04, E9 DDR_D00, E12 DDR_A12, E14 DDR_A03, E16 DDR_D19, E17 DDR_D23, E19 DDR_D31, F10 DDR_A13, F11 DDR_A06, F12 DDR_A08, F13 DDR_A02
part D pins: A6 *DDR_DQS[1], A7 DDR_DQS[1], A8 *DDR_DQS[0], A9 DDR_DQS[0], A16 *DDR_DQS[2], A17 DDR_DQS[2], A19 *DDR_DQS[3], A20 DDR_DQS[3], A21 DDR_DQGATE3, B6 DDR_DQGATE1, B8 DDR_DQM[0], B12 DDR_BA[1], B21 DDR_DQM[3], C11 DDR_VREF, C12 DDR_BA[0], D5 DDR_DQM[1], D7 DDR_DQGATE0, E11 DDR_BA[2], E15 DDR_DQM[2], E18 DDR_DQGATE2, F2 DEVICEENABLE0/AEA20, F3 BOOTMODE0/AEA11, F4 BOOTMODE1/AEA12, F5 BOOTMODE2/AEA13, G2 FASTBOOT/AEA21, G3 EMIFAWIDTH/AEA22, G4 AECLKINSEL/AEA17, G5 PCI66/AEA18, G6 BOOTMODE3/AEA14, H3 HPIWIDTH/AEA16, H4 AEA23 (out), H5 AEA19 (out), H6 RSV_BOOT/AEA15, J3 VP4D15/AEA05, J4 VP4D16/AEA06, J5 VP4D17/AEA07, J6 VP4D18/AEA08, K3 VP4D09/AEA01, K4 VP4D12/AEA02, K5 VP4D14/AEA04, K6 VP4D19/AEA09, L5 VP4D08/AEA00, L6 VP4D13/AEA03, M5 VP4D04/AEA10
part E pins: AA1 VP2CTL0, AA2 VP2D03, AA12 *PREQ/GP03, AA14 PIDSEL/GP06, AA17 *PTRDY/GP05, AB1 VP2CLK0 (in), AB2 VP2CTL1, AC20 *PCBE0/GP04, C22 T1OUT12/GP11, D21 T0OUT12/GP09, E20 T0INP12/GP08, E21 T1INP12/GP10, J1 VP4CTL1/ABA1, J2 VP4CTL0/ABA0, K1 VP4CLK1, K2 VP4CTL2/*ASADS/*ASRE, L1 VP4CLK0/AARDY (in), L2 VP4D02/*ABE00, L3 VP4D06/*ACE2, L4 VP4D07/*ACE3, M4 VP4D03/*ABE01, M6 VP4D05, M18 VP1D16/GP28, M19 VP1D19/GP31, M20 VP1D15/GP27, M21 VP1D18/GP30, N18 VP1D17/GP29, N19 VP1D12/GP24, N20 VP1D09/GP23, N21 VP1D08/GP22, N22 VP1CTL2, N23 VP1CLK1, P1 VP3CLK1/AECLKOUT, P2 VP3CTL2/*AAOE/*ASOE, P18 VP1D04/GP18, P19 VP1D03/GP17, P20 VP1D14/GP26, P21 VP1D13/GP25, P22 VP1CTL1, P23 VP1CLK0 (in), R1 VP3CTL1/AR/*W, R18 VP0D19, R19 VP1D02/GP16, R20 VP1D07/GP21, R21 VP1D06/GP20, R22 VP1D05/GP19, R23 VP1CTL0, T1 VP3CLK0/AECLKIN (in), T2 VP3CTL0/*AAWE/*ASWE, T18 VP0D07, T19 VP0D13/GP13, T20 VP0D14/GP14, T21 VP0D15/GP15, U6 VP2D05, U12 *PRST/GP01, U13 *PGNT/GP00, U18 VP0D04, U19 VP0D08, U20 VP0D16, U21 VP0D18, U22 VP0D17, U23 VP0CTL2, V5 VP2D08, V12 *PINTA/GP02, V18 VP0D03, V19 VP0D05, V20 VP0D09, V21 VP0D12/GP12, V22 VP0CTL1, V23 VP0CLK1, W1 VP2CLK1/VCLK, W3 VP2D07, W4 VP2D09, W5 VP2D02, W20 VP0D02, W21 VP0D06, Y1 VP2CTL2/*VSCRUN, Y2 VP2D06, Y3 VP2D04, Y14 *PCBE3/GP07, Y22 VP0CTL0, Y23 VP0CLK0 (in)
part F pins: AA4 AXR6, AA5 VDAC/AXR9, AA6 AXR2, AA13 AD28/HD28, AA15 AD18/HD18, AA18 AD15/HD15, AA19 AD13/HD13, AA20 AD09/HD09, AA21 AD06/HD06, AA22 AD00/HD00, AA23 AD03/HD03, AB4 AXR3, AB6 AXR0, AB13 AD27/HD27, AB14 AD23/HD23, AB15 AD17/HD17, AB18 AD12/HD12, AB20 AD08/HD08, AB21 AD05/HD05, AB22 AD01/HD01, AC13 AD26/HD26, AC14 AD22/HD22, AC18 AD14/HD14, AC21 AD02/HD02, AC22 AD04/HD04, N4 VP3D17/AED13, N5 VP3D19/AED15, N6 VP3D18/AED14, P3 VP3D16/AED12, P4 VP3D15/AED11, P5 VP3D14/AED10, P6 VP3D13/AED09, R2 VP3D12/AED08, R3 VP3D09/AED07, R4 VPED08/AED06, R5 VPED07/AED05, R6 VP3D06/AED04, T3 VP3D05/AED03, T4 VP3D04/AED02, T5 VP3D03/AED01, T6 VP3D02/AED00, U1 VP2D15/VRXD3, U2 VP2D17/VTXD1, U3 VP2D16/VTXD0, U4 VP2D19/VTXD3, U5 VP2D18/VTXD2, V3 VP2D13/VRXD1, V4 VP2D14/VRXD2, V6 AXR7, V7 AXR5, V13 AD31/HD31, V14 AD25/HD25, V15 AD21/HD21, W2 VP2D12/VRXD0, W13 AD30/HD30, W14 AD24/HD24, W15 AD20/HD20, Y5 AXR4, Y6 AXR1, Y7 STCLK/AXR8, Y13 AD29/HD29, Y15 AD19/HD19, Y16 AD16/HD16, Y19 AD11/HD11, Y20 AD10/HD10, Y21 AD07/HD07
part G pins: A1 VSS (power), A5 VSS (power), A15 VSS (power), A18 VSS (power), A23 VSS (power), AA3 VSS (power), AA8 VSS (power), AB5 VSS (power), AC1 VSS (power), AC8 VSS (power), B1 DVDD18 (power), B2 VDD18MON (power), B5 DVDD18 (power), C3 DVDD18 (power), C4 VSS (power), D9 VSS (power), D12 VSS (power), D20 VSS (power), E5 DVDD18 (power), E6 VSS (power), E23 VSS (power), F7 VSS (power), F8 DVDD18 (power), F15 VSS (power), F17 VSS (power), F19 VSS (power), G1 DVDD33 (power), G8 VSS (power), G9 DVDD18 (power), H1 VSS (power), H9 CVDD1 (power), J7 DVDD33 (power), J8 VSS (power), J9 CVDD (power), K7 VSS (power), K8 DVDD33 (power), K9 VSS (power), L7 DVDD33 (power), L8 VSS (power), L9 CVDD (power), M7 VSS (power), M8 DVDD33 (power), M9 VSS (power), N1 VSS (power), N2 DVDD33 (power), N8 VSS (power), P7 VSS (power), P9 VSS (power), T7 VSS (power), T9 VSS (power), V1 VSS (power), V9 VSS (power), W7 VSS (power), Y9 VSS (power)
part H pins: AB7 DVDD33 (power), AB8 AVDDT (power), AC2 DVDD33 (power), AC5 DVDD33 (power), B10 AVDLL1 (power), B15 DVDD18 (power), B18 DVDD18 (power), B22 AVDLL2 (power), B23 DVDD18 (power), C10 DVDD18 (power), C13 DVDD18 (power), C21 DVDD18 (power), E22 DVDD33 (power), F14 DVDD18 (power), F16 DVDD18 (power), F18 DVDD18 (power), F20 DVDD33 (power), G7 PLLV2, G10 VSS (power), G11 DVDD18 (power), G12 VSS (power), G13 DVDD18 (power), G14 VSS (power), G15 DVDD18 (power), G16 VSS (power), G17 DVDD18 (power), G18 VSS (power), G19 DVDD33 (power), G21 VDD33MON (power), G22 VSS (power), H10 DVDD18 (power), H11 VSS (power), H12 DVDD18 (power), H13 VSS (power), H14 DVDD18 (power), H15 VSS (power), H16 DVDD33 (power), H17 VSS (power), N3 PLLV1, N7 DVDD33 (power), N9 CVDD (power), P8 DVDD33 (power), R7 DVDD33 (power), R8 CVDD (power), R9 CVDDESS (power), T8 DVDD33 (power), V2 DVDD33 (power), V8 CVDD (power), Y4 DVDD33 (power), Y8 DVDD33 (power)
part I pins: H22 DVDD33 (power), J10 VSS (power), J11 CVDD (power), J12 VSS (power), J13 CVDD1 (power), J14 VSS (power), J15 CVDD (power), J16 VSS (power), J17 DVDD33 (power), K10 CVDD (power), K11 VSS (power), K12 CVDD (power), K13 VSS (power), K14 CVDD (power), K15 VSS (power), K16 DVDD33 (power), K17 VSS (power), L10 VSS (power), L11 CVDD (power), L12 VSS (power), L13 CVDD (power), L14 VSS (power), L15 CVDD (power), L16 VSS (power), L17 DVDD33 (power), L19 VCCMON (power), M10 CVDD (power), M11 VSS (power), M12 CVDD (power), M13 VSS (power), M14 CVDD (power), M15 VSS (power), M16 DVDD33 (power), M17 VSS (power), M22 VSS (power), M23 DVDD33 (power), N10 VSS (power), N11 CVDD (power), N12 VSS (power), N13 CVDD (power), N14 VSS (power), N15 CVDD (power), N16 VSS (power), N17 DVDD33 (power), P10 CVDD (power), P11 VSS (power), P12 CVDD (power), P13 VSS (power), P14 CVDD (power), P15 VSS (power), P16 DVDD33 (power), P17 VSS (power)
part J pins: AA11 VSS (power), AB10 AVDDR (power), AB12 DVDD33 (power), AB16 DVDD33 (power), AB19 VSS (power), AB23 VSS (power), AC10 VSS (power), AC12 VSS (power), AC16 VSS (power), AC19 DVDD33 (power), AC23 DVDD33 (power), R10 VSS (power), R11 CVDDESS (power), R12 VSS (power), R13 CVDD (power), R14 VSS (power), R15 CVDD (power), R16 VSS (power), R17 DVDD33 (power), T10 DVDDD (power), T11 VSS (power), T12 DVDD33 (power), T13 VSS (power), T14 DVDD33 (power), T15 VSS (power), T16 CVDD (power), T17 VSS (power), T22 VSS (power), T23 DVDD33 (power), U10 DVDDD (power), U11 AVDDT (power), U14 VSS (power), U15 DVDD33 (power), U16 VSS (power), U17 DVDD33 (power), V11 AVDDA (power), V16 DVDD33 (power), V17 VSS (power), W10 AVDDA (power), W22 VSS (power), W23 DVDD33 (power), Y10 VSS (power)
